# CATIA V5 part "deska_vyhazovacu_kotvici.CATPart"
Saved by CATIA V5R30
Part number: Deska_vyhazovacu_kotvici
Definition: F 80_346446_218_17_1730
Nomenclature: F 80_346446_218_17_1730
Source: Unknown
Description: PART--DESC
Bounding box of the stored display mesh (mm): x -223 to 223, y -109 to 109, z -198 to -181
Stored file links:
  E:\Bakalarka\Model\Forma_v7\deska_vyhazovacu_kotvici.CATPart
  E:\Bakalarka\Model\Forma_v7\Sestava_vyhazovacu.CATProduct
  E:\Bakalarka\Model\Chyba catie 2\Forma_Sestava_vyhazovacu.CATPart
  E:\Bakalarka\Model\Forma_v7\Forma_Sestava_vyhazovacu.CATPart
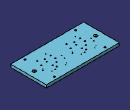
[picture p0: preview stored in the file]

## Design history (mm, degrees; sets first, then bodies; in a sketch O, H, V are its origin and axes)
Body1 "MANIFOLD_SOLID_BREP #4090" (main body)
  Solid1: solid without history
  Body2 "Result of __DrillHole"
    Solid2: linked copy from another document
  Assemble1 "DrillHoleEjector_E1710_2.1": tool Body2
  Body3 "Result of __DrillHole"
    Solid3: linked copy from another document
  Assemble2 "DrillHoleEjector_E1710_3.1": tool Body3
  Body4 "Result of __DrillHole"
    Solid4: linked copy from another document
  Assemble3 "DrillHoleEjector_E1710_4.1": tool Body4
  Body5 "Result of __DrillHole"
    Solid5: linked copy from another document
  Assemble4 "DrillHoleEjector_E1710_5.1": tool Body5
  Body6 "Result of __DrillHole"
    Solid6: linked copy from another document
  Assemble5 "DrillHoleEjector_E1710_6.1": tool Body6
  Body7 "Result of __DrillHole"
    Solid7: linked copy from another document
  Assemble6 "DrillHoleEjector_E1710_7.1": tool Body7
  Body8 "Result of __DrillHole"
    Solid8: linked copy from another document
  Assemble7 "DrillHoleEjector_E1710_8.1": tool Body8
  Body9 "Result of __DrillHole"
    Solid9: linked copy from another document
  Assemble8 "DrillHoleEjector_E1710_9.1": tool Body9
  Body10 "Result of __DrillHole"
    Solid10: linked copy from another document
  Assemble9 "DrillHoleEjector_E1710_10.1": tool Body10
  Body11 "Result of __DrillHole"
    Solid11: linked copy from another document
  Assemble10 "DrillHoleEjector_E1710_11.1": tool Body11
  Body12 "Result of __DrillHole"
    Solid12: linked copy from another document
  Assemble11 "DrillHoleEjector_E1710_1.1": tool Body12
  Body13 "Result of __DrillHole"
    Solid13: linked copy from another document
  Assemble12 "DrillHoleEjector_E1710_13.1": tool Body13
  Body14 "Result of __DrillHole"
    Solid14: linked copy from another document
  Assemble13 "DrillHoleEjector_E1710_14.1": tool Body14
  Body15 "Result of __DrillHole"
    Solid15: linked copy from another document
  Assemble14 "DrillHoleEjector_E1710_15.1": tool Body15
  Body16 "Result of __DrillHole"
    Solid16: linked copy from another document
  Assemble15 "DrillHoleEjector_E1710_23.1": tool Body16
  Body17 "Result of __DrillHole"
    Solid17: linked copy from another document
  Assemble16 "DrillHoleEjector_E1710_24.1": tool Body17
  Body18 "Result of __DrillHole"
    Solid18: linked copy from another document
  Assemble17 "DrillHoleEjector_E1710_25.1": tool Body18
  Body19 "Result of __DrillHole"
    Solid19: linked copy from another document
  Assemble18 "DrillHoleEjector_E1710_26.1": tool Body19
  Body20 "Result of __DrillHole"
    Solid20: linked copy from another document
  Assemble19 "DrillHoleEjector_E1710_27.1": tool Body20
  Body21 "Result of __DrillHole"
    Solid21: linked copy from another document
  Assemble20 "DrillHoleEjector_E1710_28.1": tool Body21
  Body22 "Result of __DrillHole"
    Solid22: linked copy from another document
  Assemble21 "DrillHoleEjector_E1710_29.1": tool Body22
  Body23 "Result of __DrillHole"
    Solid23: linked copy from another document
  Assemble22 "DrillHoleEjector_E1710_31.1": tool Body23
  Body24 "Result of __DrillHole"
    Solid24: linked copy from another document
  Assemble23 "DrillHoleEjector_E1710_32.1": tool Body24
  Body25 "Result of __DrillHole"
    Solid25: linked copy from another document
  Assemble24 "DrillHoleEjector_E1710_33.1": tool Body25
  Body26 "Result of __DrillHole"
    Solid26: linked copy from another document
  Assemble25 "DrillHoleEjector_E1710_34.1": tool Body26
  Body27 "Result of __DrillHole"
    Solid27: linked copy from another document
  Assemble26 "DrillHoleEjector_E1710_35.1": tool Body27
  Body28 "Result of __DrillHole"
    Solid28: linked copy from another document
  Assemble27 "DrillHoleEjector_E1710_36.1": tool Body28
  Body29 "Result of __DrillHole"
    Solid29: linked copy from another document
  Assemble28 "DrillHoleEjector_E1710_37.1": tool Body29
  DatumCurve1 to DatumCurve4
  DatumSurface1
  Sketch1 on face of Solid1, origin (0, 0, -198), H (1, 0, 0), V (0, -1, 0)
    reference projected circle E1 centre (113.5, -54.5) radius 4 from edge of DatumCurve1
    reference projected circle E2 centre (156, -21.5) radius 4 from edge of DatumCurve2
    reference projected circle E3 centre (20.5, 0) radius 4 from edge of DatumCurve4
    reference projected circle E4 centre (25.5, -22.5) radius 4 from face of DatumSurface1
    point P1 (55, 53)
    circle A1 centre (156, -21.5) radius 4.5
    point P2 (156, -21.5)
    circle A2 centre (113.5, -54.5) radius 4.5
    point P3 (113.5, -54.5)
    circle A3 centre (25.5, -22.5) radius 4.5
    point P4 (25.5, -22.5)
    circle A4 centre (20.5, 0) radius 4.5
    point P5 (20.5, 0)
    radius A3 = 4.5
    radius A4 = 4.5
    radius A2 = 4.5
    radius A1 = 4.5
    concentricity: P2 E2, P3 E1, P4 E4, P5 E3
  Pocket1: profile Sketch1, direction (0, 0, 1), length 3
  DatumCurve5 to DatumCurve7
  DatumSurface2 to DatumSurface5
  DatumPoint1
  Sketch2 on end face of Pocket1, origin (0, 0, -195), H (1, 0, 0), V (0, -1, 0)
    reference projected circle E1 centre (55, 53) radius 4 from edge of DatumCurve6
    reference projected circle E2 centre (156, -21.5) radius 4 from edge of DatumCurve7
    reference projected circle E3 centre (113.5, -54.5) radius 4 from face of DatumSurface2
    reference projected circle E4 centre (25.5, -22.5) radius 4 from face of DatumSurface3
    reference projected circle E5 centre (20.5, 0) radius 4 from face of DatumSurface4
    reference projected circle E6 centre (-24, -21.5) radius 4 from face of DatumSurface5
    point P1 (55, 53)
    circle A1 centre (156, -21.5) radius 2.25
    point P2 (156, -21.5)
    circle A2 centre (113.5, -54.5) radius 2.25
    point P3 (113.5, -54.5)
    circle A3 centre (25.5, -22.5) radius 2.25
    point P4 (25.5, -22.5)
    circle A4 centre (20.5, 0) radius 2.25
    point P5 (20.5, 0)
    circle A5 centre (-24, -21.5) radius 2.25
    point P6 (-24, -21.5)
    radius A3 = 2.25
    radius A4 = 2.25
    radius A1 = 2.25
    radius A2 = 2.25
    radius A5 = 2.25
    concentricity: P1 E1, P2 E2, P3 E3, P4 E4, P5 E5, P6 E6
  Pocket2: profile Sketch2, direction (0, 0, 1), length 14
  Body30 "Result of __DrillHole"
    Solid30: linked copy from another document
  Assemble29 "DrillHoleEjector_E1710_1.2": tool Body30
  Body31 "Result of __DrillHole"
    Solid31: linked copy from another document
  Assemble30 "DrillHoleEjector_E1710_2.2": tool Body31
  Body32 "Result of __DrillHole"
    Solid32: linked copy from another document
  Assemble31 "DrillHoleEjector_E1710_3.2": tool Body32
  Body33 "Result of __DrillHole"
    Solid33: linked copy from another document
  Assemble32 "DrillHoleEjector_E1710_4.2": tool Body33
  Body34 "Result of DrillHole"
    Solid34: linked copy from another document
  Assemble33 "DrillHoleLeaderPin_E1010_1.1": tool Body34
  Body35 "Result of DrillHole"
    Solid35: linked copy from another document
  Assemble34 "DrillHoleLeaderPin_E1010_1.2": tool Body35
  Body36 "Result of DrillHole"
    Solid36: linked copy from another document
  Assemble35 "DrillHoleBushing_E1105_1.3": tool Body36
  Body37 "Result of DrillHole"
    Solid37: linked copy from another document
  Assemble36 "DrillHoleBushing_E1105_1.4": tool Body37
  Body38 "Result of DrillHole"
    Solid38: linked copy from another document
  Assemble37 "DrillHoleLeaderPin_E1010_1.3": tool Body38
  Body39 "Result of DrillHole"
    Solid39: linked copy from another document
  Assemble38 "DrillHoleLeaderPin_E1010_1.4": tool Body39
  Sketch3 on face of Solid1, origin (0, 0, -198), H (1, 0, 0), V (0, -1, 0)
    point P1 (-88, 31)
    point P2 (-80, 12)
    reference projected line E1 (223, 109) -> (-223, 109) from edge [face of Solid1 | face of Solid1]
    reference projected line E2 (-223, 109) -> (-223, -109) from edge [face of Solid1 | face of Solid1]
    point P3 (92, 31)
    point P4 (100, 12)
    distance P1 E1 = 78
    distance P1 E2 = 135
    distance P2 E1 = 97
    distance P2 E2 = 143
    distance P3 P1 V = 0
    distance P3 E2 = 315
    distance P4 P2 V = 0
    distance P4 E2 = 323
  DatumPoint2
  DatumPoint3
  Sketch4 on face of Solid1, origin (0, 0, -198), H (1, 0, 0), V (0, -1, 0)
    projected point E1 (188, 0) from vertex of DatumPoint2
    projected point E2 (-188, 0) from vertex of DatumPoint3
